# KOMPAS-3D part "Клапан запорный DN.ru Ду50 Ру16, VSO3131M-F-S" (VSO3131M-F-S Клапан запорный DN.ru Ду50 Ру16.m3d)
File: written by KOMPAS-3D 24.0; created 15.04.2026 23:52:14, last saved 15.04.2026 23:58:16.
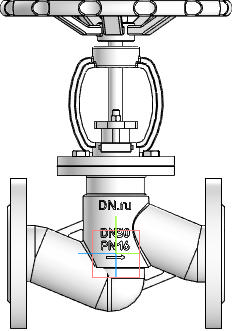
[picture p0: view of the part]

Document properties: Автор: R2D2; Полное имя файла: E:\Работа\Зайцев\VSO3131M-F-S Клапан запорный DN.ru Ду15-100 Ру16\DN50\VSO3131M-F-S Клапан запорный DN.ru Ду50 Ру16.m3d

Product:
- Part/product: Клапан запорный DN.ru Ду50 Ру16  | designation VSO3131M-F-S
    Масса: 10.5
    Раздел спецификации: Прочие изделия
    Примечание: D090-02951

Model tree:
1. Операция без истории:1

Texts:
  VSO3131M-F-S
